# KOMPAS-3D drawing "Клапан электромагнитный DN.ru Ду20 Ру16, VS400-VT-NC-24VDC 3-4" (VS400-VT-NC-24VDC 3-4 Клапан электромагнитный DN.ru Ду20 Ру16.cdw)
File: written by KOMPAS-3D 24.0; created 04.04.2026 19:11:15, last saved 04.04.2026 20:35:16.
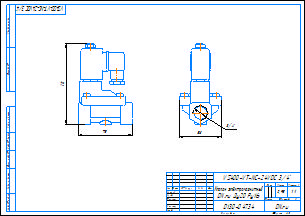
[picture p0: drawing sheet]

Document properties: c3d_UniqueCompID: ef56311e-7521-43dc-8291-0e6108b3d81d; Обозначение: VS400-ET-NC-220VAC 1-2; Наименование: Клапан электромагнитный DN.ru Ду15 Ру16; Автор: artio; Класс точности: c; Знак неуказанной шероховатости: Шероховатость не задана; Рассекать на разрезах: Да; c3d_UniqueCompID: ef56311e-7521-43dc-8291-0e6108b3d81d; Обозначение: VS400-ET-NC-220VAC 3-4; Наименование: Клапан электромагнитный DN.ru Ду20 Ру16; Автор: artio; Класс точности: c; Знак неуказанной шероховатости: Шероховатость не задана; Рассекать на разрезах: Да; c3d_UniqueCompID: ef56311e-7521-43dc-8291-0e6108b3d81d; Обозначение: VS400-ET-NC-220VAC 3-8; Наименование: Клапан электромагнитный DN.ru Ду10 Ру16; Автор: artio; Класс точности: c; Знак неуказанной шероховатости: Шероховатость не задана; Рассекать на разрезах: Да; Автор: artio; Форматы листов документа: A3; Полное имя файла: VS400-VT-NC-24VDC 3-4 Клапан электромагнитный DN.ru Ду20 Ру16.m3d; Масса: 0.954; Наименование: Клапан электромагнитный DN.ru Ду20 Ру16; Количество листов документа: 1; Примечание: D130-04734

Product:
- Body: Тело 1  | qty 1
    Масса: 1.210539
- Part/product: Клапан электромагнитный DN.ru Ду20 Ру16  | designation VS400-VT-NC-24VDC 3-4
    Масса: 0.954
    Раздел спецификации: Прочие изделия
    Примечание: D130-04734
    additional columns: ef56311e-7521-43dc-8291-0e6108b3d81d; VS400-ET-NC-220VAC 3-4; artio; c; Шероховатость не задана; Да

Views: Вид 1, Спереди, Проекционный вид 2
Referenced files in C:\Users\artio\OneDrive\Рабочий стол\Клапан электромагнитный DN.ru\VS400-ET-NC\VS400-ET-NC-24VDC\: VS400-ET-NC-24VDC 3-8 Клапан электромагнитный DN.ru Ду10 Ру16.m3d
Referenced files in C:\Users\artio\OneDrive\Рабочий стол\Клапан электромагнитный DN.ru\VS400-VT-NC\VS400-VT-NC-24VDC\: VS400-VT-NC-24VDC 3-4 Клапан электромагнитный DN.ru Ду20 Ру16.m3d
Referenced files in C:\Users\artio\OneDrive\Рабочий стол\Клапан электромагнитный DN.ru\VS400-ET-NC\: VS400-ET-NC-24VDC 3-8 Клапан электромагнитный DN.ru Ду10 Ру16.cdw
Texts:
  VS400-VT-NC-24VDC 3-4
  Клапан электромагнитный
  DN.ru Ду20 Ру16
  VS400-VT-NC-24VDC 3/4"
  VS400-VT-NC-24VDC 3/4"-
  Клапан электромагнитный DN.ru Ду20 Ру16
  VS400-VT-NC-24VDC 3-4 Клапан электромагнитный DN.ru Ду20 Ру16
Dimensions and other numbers on the sheet: 0; 3; 2; 4; 58; 3/4"; 75; 112; 1:1; 1; 0,95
